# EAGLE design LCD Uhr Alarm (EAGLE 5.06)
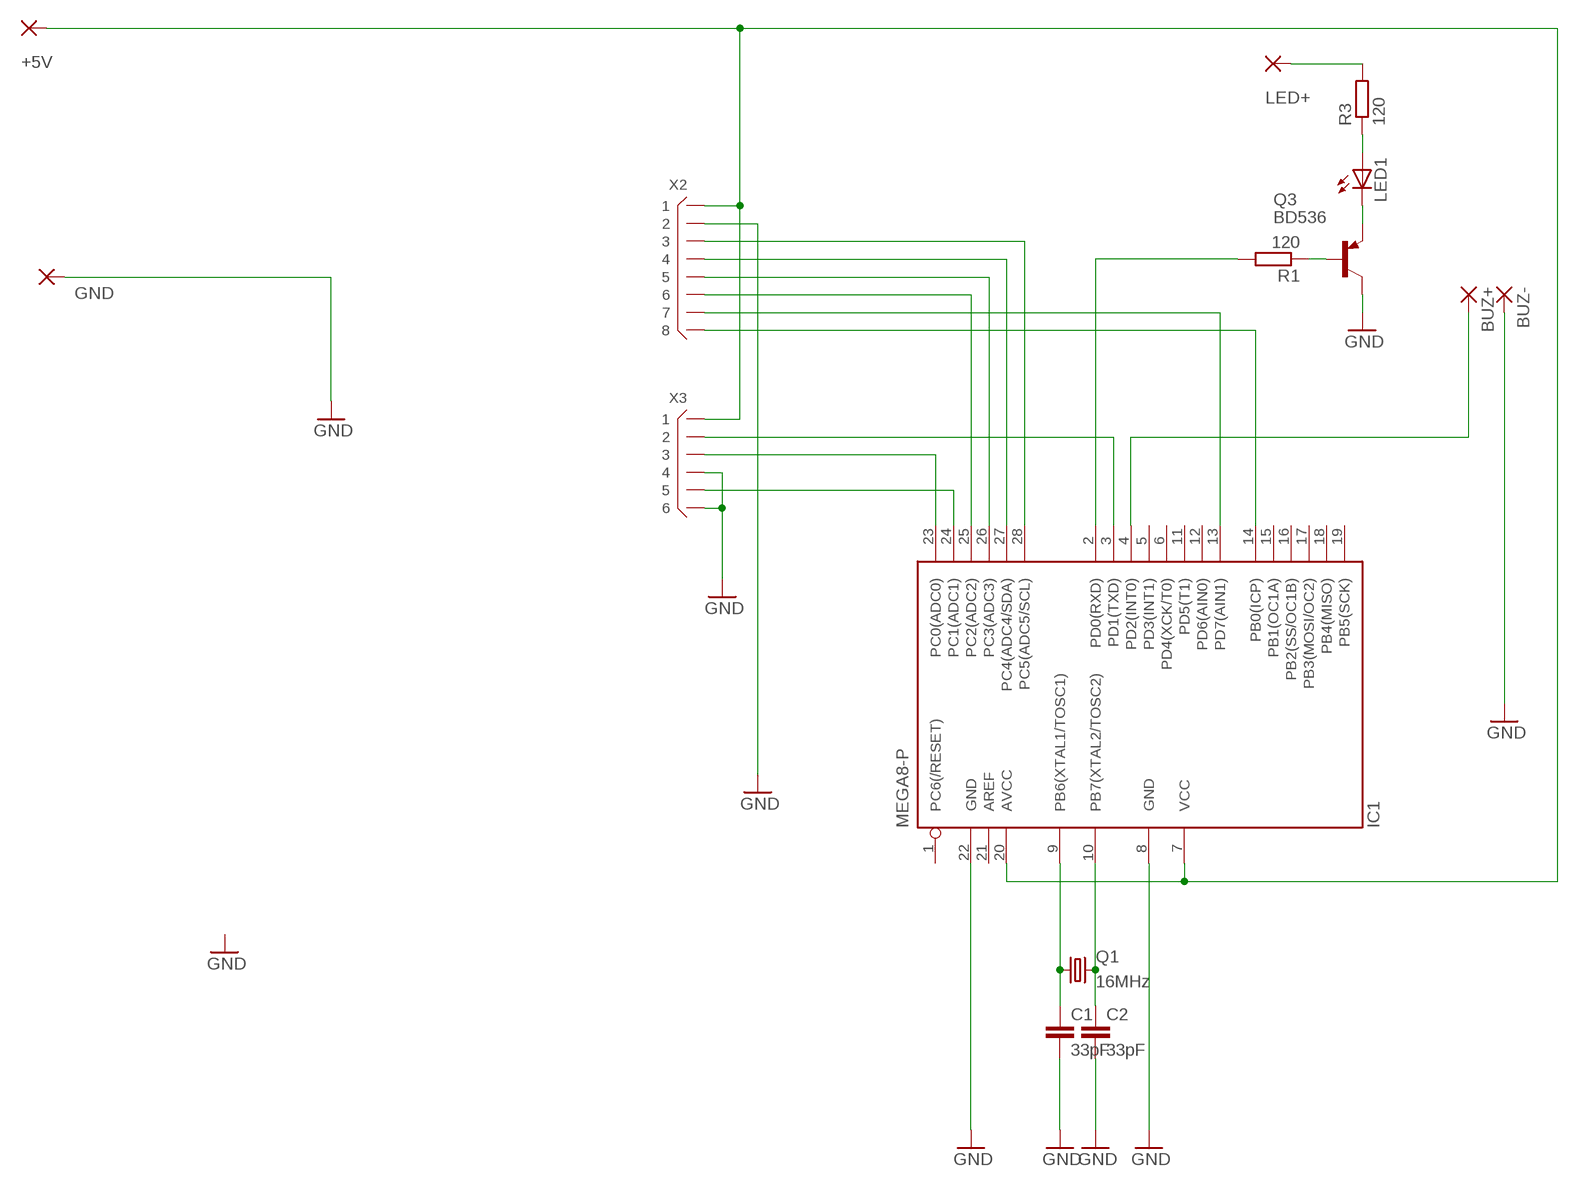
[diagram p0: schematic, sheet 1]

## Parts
+5V  WIREPAD2,54/1,0  [2,54/1,0]
BUZ+  WIREPAD2,54/1,0  [2,54/1,0]
BUZ-  WIREPAD2,54/1,0  [2,54/1,0]
C1  33pF  C2,5-3  [C2.5-3]
C2  33pF  C2,5-3  [C2.5-3]
GND  WIREPAD2,54/1,0  [2,54/1,0]
IC1  MEGA8-P  [DIL28-3]
LED1  LED5MM  [LED5MM]
LED+  WIREPAD2,54/1,0  [2,54/1,0]
Q1  16MHz  CRYSTALHC18U-V  [HC18U-V]
Q3  BD536  [TO220]
R1  120  R-EU_0207/10  [0207/10]
R3  120  R-EU_0207/10  [0207/10]
X2  X08L  [X08L-SIL]
X3  X06L  [X06L-SIL]

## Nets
GND: BUZ-.1(P) C1.2 C2.2 GND.1(P) IC1.8(GND) IC1.22(GND) Q3.2(C) X2.2 X3.4 X3.6
N$1: IC1.13(PD7(AIN1)) X2.7
N$2: +5V.1(P) IC1.7(VCC) IC1.20(AVCC) X2.1 X3.1
N$3: IC1.28(PC5(ADC5/SCL)) X2.3
N$4: LED1.A R3.1
N$5: IC1.27(PC4(ADC4/SDA)) X2.4
N$6: IC1.26(PC3(ADC3)) X2.5
N$7: IC1.25(PC2(ADC2)) X2.6
N$8: IC1.14(PB0(ICP)) X2.8
N$9: LED1.K(C) Q3.3(E)
N$10: Q3.1(B) R1.1
N$11: IC1.2(PD0(RXD)) R1.2
N$12: IC1.3(PD1(TXD)) X3.2
N$13: C2.1 IC1.10(PB7(XTAL2/TOSC2)) Q1.2
N$14: C1.1 IC1.9(PB6(XTAL1/TOSC1)) Q1.1
N$15: IC1.23(PC0(ADC0)) X3.3
N$16: IC1.24(PC1(ADC1)) X3.5
N$17: BUZ+.1(P) IC1.4(PD2(INT0))
N$18: LED+.1(P) R3.2
Unconnected: IC1.1(PC6(/RESET)) IC1.5(PD3(INT1)) IC1.6(PD4(XCK/T0)) IC1.11(PD5(T1)) IC1.12(PD6(AIN0)) IC1.15(PB1(OC1A)) IC1.16(PB2(SS/OC1B)) IC1.17(PB3(MOSI/OC2)) IC1.18(PB4(MISO)) IC1.19(PB5(SCK)) IC1.21(AREF)

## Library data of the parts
+5V BUZ+ BUZ- GND LED+ = wirepad:WIREPAD: Wire PAD connect wire on PCB
C1 C2 = capacitor-wima:C: CAPACITOR
IC1 = atmel:MEGA8-P: MICROCONTROLLER 8 Kbytes FLASH, 1 kbytes SRAM, 512 bytes EEPROM, USART, 4-channel 10 bit ADC, 2-channel 8 bit ADC Pin compatible with Atmega48, ATMega88, ATMega168 Source: avr.lbr
LED1 = led:LED: LED
Q1 = crystal:CRYSTAL: CRYSTAL
Q3 = transistor-pnp:BD536: PNP Transistor
R1 R3 = resistor:R-EU_: RESISTOR, European symbol
X2 = connectors:X08: Connector 8 pins
X3 = connectors:X06: Connector 6 pins

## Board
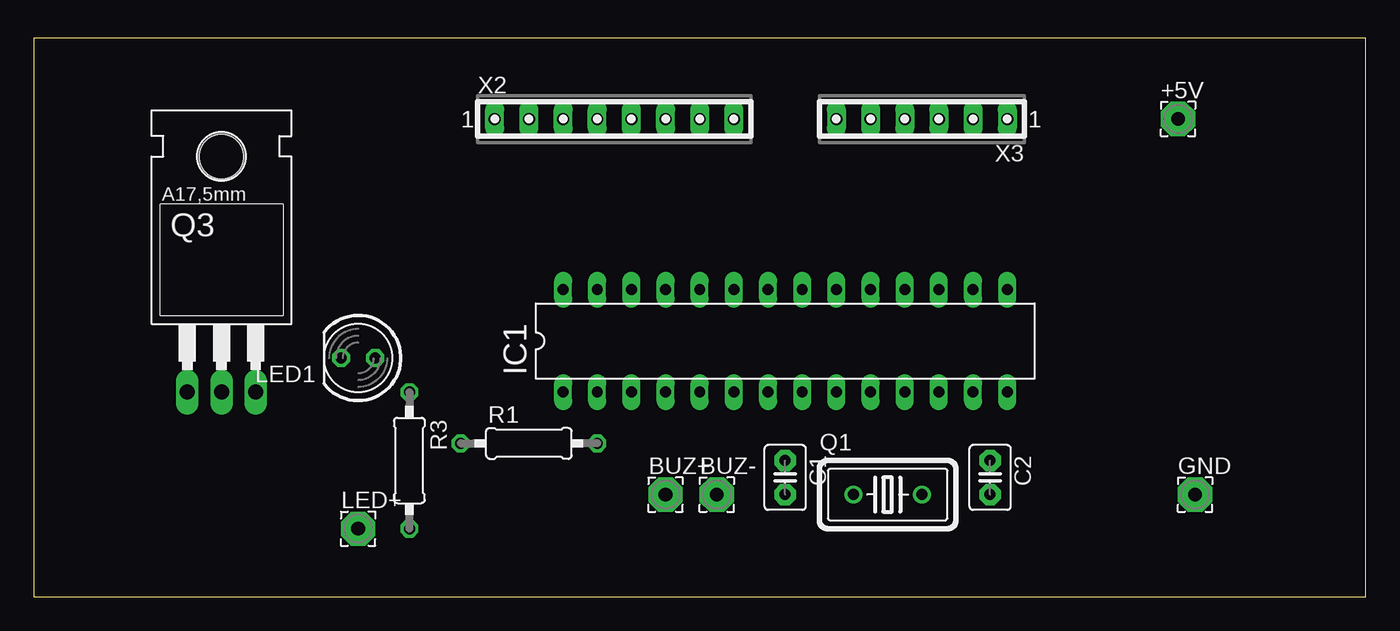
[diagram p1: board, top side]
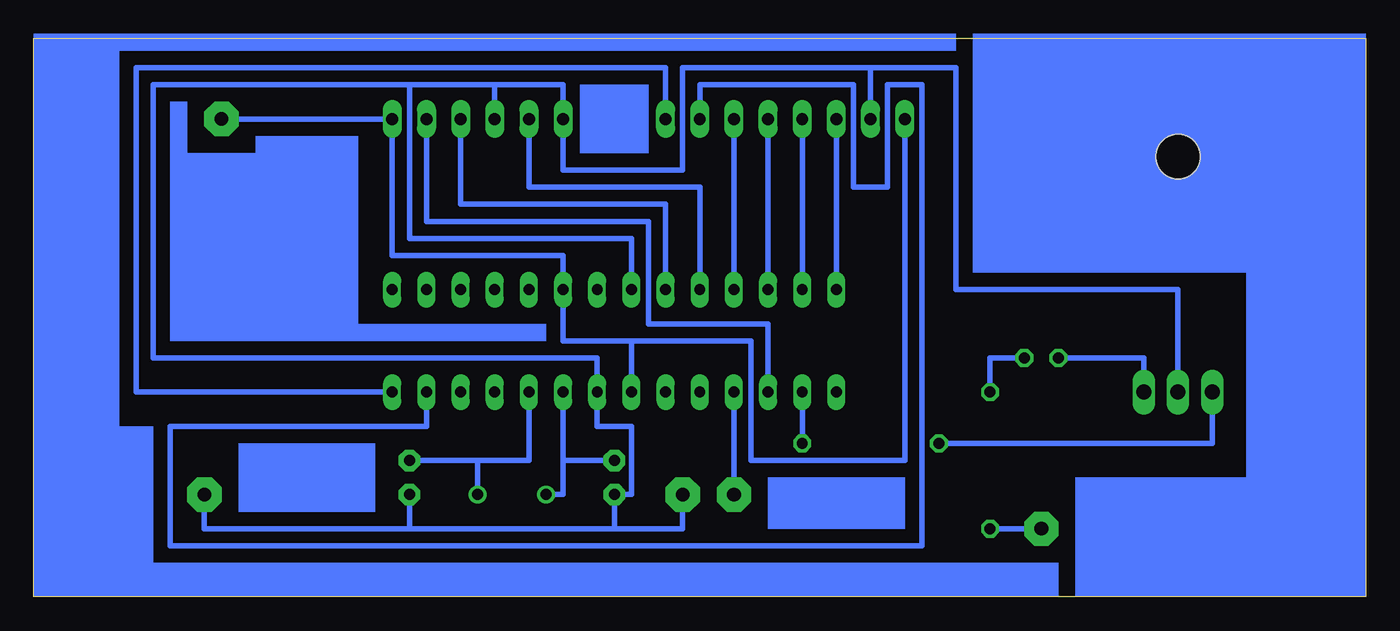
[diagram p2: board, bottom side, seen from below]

Size 99.04 x 41.58 mm. Coordinates in mm from the lower left corner, seen from the top.
Outline: 0,0 99.04,0 99.04,41.58 0,41.58 0,0
Copper layers (1*16): Top 0.035mm / dielectric 1.5mm / Bottom 0.035mm
Design rules "default": minimum track width 10mil, minimum drill 24mil, track to track 8mil, track to pad 8mil, pad to pad 8mil, via to via 8mil, smd to smd 8mil, copper to edge 40mil, drill to drill 8mil, minimum pad ring 10mil, minimum via ring 8mil, stop-mask expansion 4mil, vias tented up to drill 0mil, thermal gap 10mil

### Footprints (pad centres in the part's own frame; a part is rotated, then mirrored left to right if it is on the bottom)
2,54/1,0 = drill 1.016 pad 2.54 octagon: 1 0,0
C2.5-3 = drill 0.813 pad 1.6 octagon: 1 -1.27,0; 2 1.27,0
DIL28-3 = drill 0.813 long: 1 -16.51,-3.81; 2 -13.97,-3.81; 3 -11.43,-3.81; 4 -8.89,-3.81; 5 -6.35,-3.81; 6 -3.81,-3.81; 7 -1.27,-3.81; 8 1.27,-3.81; 9 3.81,-3.81; 10 6.35,-3.81; 11 8.89,-3.81; 12 11.43,-3.81; 13 13.97,-3.81; 14 16.51,-3.81; 15 16.51,3.81; 16 13.97,3.81; 17 11.43,3.81; 18 8.89,3.81; 19 6.35,3.81; 20 3.81,3.81; 21 1.27,3.81; 22 -1.27,3.81; 23 -3.81,3.81; 24 -6.35,3.81; 25 -8.89,3.81; 26 -11.43,3.81; 27 -13.97,3.81; 28 -16.51,3.81
LED5MM = drill 0.813 octagon: A -1.27,0; K 1.27,0
HC18U-V = drill 0.813 round: 1 -2.54,0; 2 2.54,0
TO220 = drill 1.118 long: 1 -2.54,-6.35; 2 0,-6.35; 3 2.54,-6.35 | hole 3.302: 0,11.176
0207/10 = drill 0.813 octagon: 1 -5.08,0; 2 5.08,0
X08L-SIL = drill 0.889 pad 1.397 long: 1 -8.89,0; 2 -6.35,0; 3 -3.81,0; 4 -1.27,0; 5 1.27,0; 6 3.81,0; 7 6.35,0; 8 8.89,0
X06L-SIL = drill 0.889 pad 1.397 long: 1 -6.35,0; 2 -3.81,0; 3 -1.27,0; 4 1.27,0; 5 3.81,0; 6 6.35,0

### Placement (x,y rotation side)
+5V  85.09,35.56 0 top
BUZ+  46.99,7.62 0 top
BUZ-  50.8,7.62 0 top
C1  55.88,8.89 270 top
C2  71.12,8.89 270 top
GND  86.36,7.62 0 top
IC1  55.88,19.05 0 top
LED1  24.13,17.78 180 top
LED+  24.13,5.08 0 top
Q1  63.5,7.62 0 top
Q3  13.97,21.59 0 top
R1  36.83,11.43 0 top
R3  27.94,10.16 270 top
X2  43.18,35.56 0 top
X3  66.04,35.56 180 top

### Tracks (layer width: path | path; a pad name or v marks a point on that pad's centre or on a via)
GND
  Bottom 0.406: BUZ-.1 50.8,5.08 55.88,5.08 | 55.88,5.08 C1.2 54.61,7.62 54.61,12.7 57.15,12.7 IC1.8 57.15,17.78 90.17,17.78 90.17,38.1 71.12,38.1 | 55.88,5.08 71.12,5.08 | 71.12,5.08 C2.2 | GND.1 86.36,5.08 71.12,5.08 | 64.77,38.1 71.12,38.1 | 64.77,38.1 X3.4 | 36.83,39.37 X2.2 | 36.83,39.37 50.8,39.37 50.8,31.75 59.69,31.75 X3.6 59.69,38.1 64.77,38.1 | 36.83,39.37 30.48,39.37 30.48,22.86 13.97,22.86 Q3.2 | IC1.22 54.61,26.67 71.12,26.67 71.12,38.1
N$1
  Bottom 0.406: X2.7 49.53,38.1 38.1,38.1 38.1,30.48 35.56,30.48 35.56,38.1 33.02,38.1 33.02,3.81 88.9,3.81 88.9,12.7 69.85,12.7 IC1.13
N$2
  Bottom 0.406: +5V.1 X3.1 72.39,25.4 59.69,25.4 IC1.20 59.69,19.05 54.61,19.05 | 54.61,19.05 IC1.7 | 54.61,19.05 45.72,19.05 45.72,10.16 41.91,10.16 34.29,10.16 X2.1
N$3
  Bottom 0.406: IC1.28 X2.3
N$4
  Bottom 0.406: LED1.A 27.94,17.78 R3.1
N$5
  Bottom 0.406: IC1.27 X2.4
N$6
  Bottom 0.406: IC1.26 X2.5
N$7
  Bottom 0.406: IC1.25 X2.6
N$8
  Bottom 0.406: IC1.14 91.44,15.24 91.44,39.37 52.07,39.37 X2.8
N$9
  Bottom 0.406: Q3.3 16.51,17.78 LED1.K
N$10
  Bottom 0.406: R1.1 11.43,11.43 Q3.1
N$11
  Bottom 0.406: R1.2 IC1.2
N$12
  Bottom 0.406: X3.2 69.85,27.94 53.34,27.94 53.34,20.32 44.45,20.32 IC1.3
N$13
  Bottom 0.406: 66.04,10.16 C2.1 | Q1.2 66.04,10.16 | IC1.10 62.23,10.16 66.04,10.16
N$14
  Bottom 0.406: C1.1 59.69,10.16 | 59.69,10.16 IC1.9 | Q1.1 59.69,7.62 59.69,10.16
N$15
  Bottom 0.406: IC1.23 52.07,29.21 67.31,29.21 X3.3
N$16
  Bottom 0.406: IC1.24 49.53,30.48 62.23,30.48 X3.5
N$17
  Bottom 0.406: BUZ+.1 IC1.4
N$18
  Bottom 0.406: LED+.1 R3.2
(copper drawn outside any net)
  shapes: Bottom area x17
